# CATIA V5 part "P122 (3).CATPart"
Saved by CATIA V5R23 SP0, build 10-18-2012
Part number: 05-LICP-T02-E-S11-P122 (3)
Definition: butee a aiguilles
Description: butee_a_aiguilles_ax_5_40_60_03
Bounding box of the stored display mesh (mm): x 1.687 to 4.7, y -29.961 to 29.961, z -29.961 to 29.961
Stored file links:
  C:\wamp\www\COURS\CONCEPTION GMP1\TITRE 02-SEMESTRE 2\03-TP7-PRESSE MECANIQUE\eleve\P122 (3).CATPart
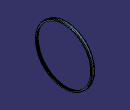
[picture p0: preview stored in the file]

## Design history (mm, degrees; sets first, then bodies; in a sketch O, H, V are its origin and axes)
Body1 (main body)
  Solid1: solid without history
